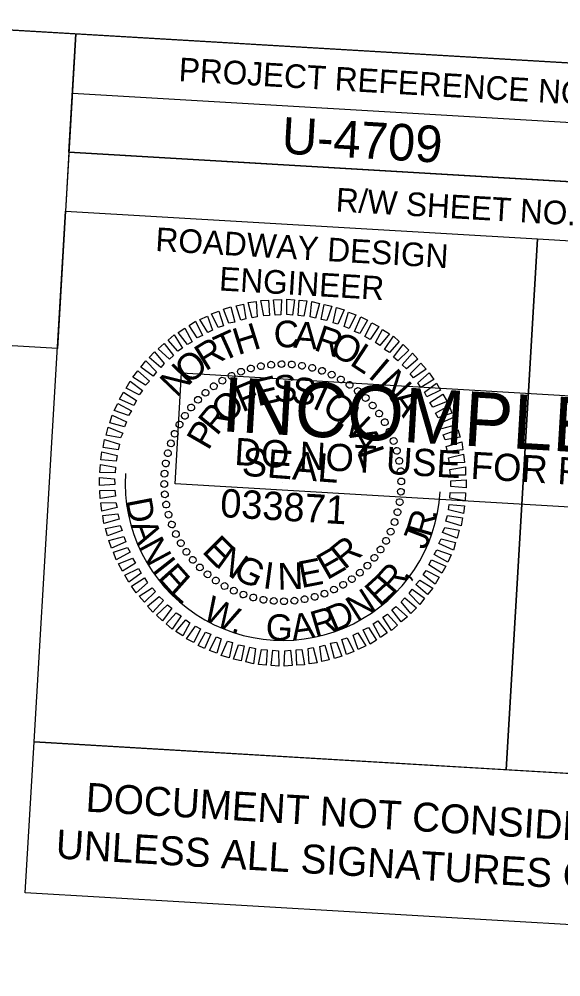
# Model space of a CAD drawing. Extents: x 2012145 to 2014096, y 444445 to 445643.
# Drawn here: x 2013858 to 2013972.6, y 445331.9 to 445534.5 of the extents above; entities that cross this region are included whole.
import ezdxf

# ---------------------------------------------------------------- set-up
doc = ezdxf.new("R2010")
doc.units = 0
for name, color, linetype in [('Old_Level_58', 7, 'Continuous'), ('Scratch_Level_0', 7, 'Continuous'), ('Sheet Data Field CELL', 7, 'Continuous'), ('Sheet Plan And Profile CELL', 7, 'Continuous'), ('Sheet Professional Seal CELL', 7, 'Continuous'), ('Sheet Profile Grid Minor CELL', 7, 'Continuous'), ('Sheet Sticker Exception Certification CELL', 7, 'Continuous'), ('Sheet Sticker Incomplete CELL', 7, 'Continuous')]:
    doc.layers.add(name, color=color, linetype=linetype)

msp = doc.modelspace()

# ---------------------------------------------------------------- linework, layer by layer
at = {"layer": 'Old_Level_58'}
msp.add_lwpolyline([(2013670.27, 445543.15), (2013869.97, 445531.38), (2013866.05, 445464.8), (2013666.34, 445476.57)], close=True, dxfattribs=at)
at = {"layer": 'Scratch_Level_0'}
msp.add_arc((2013913.73, 445436.43), 33.36, 176.6264, 356.6264, dxfattribs=at)
at = {"layer": 'Sheet Plan And Profile CELL'}
for p, q in [((2013869.23, 445518.85), (2014068.93, 445507.08)), ((2013868.5, 445506.37), (2013867.76, 445493.89)), ((2013868.5, 445506.37), (2014068.2, 445494.6)), ((2013967.64, 445488), (2013961.02, 445375.75))]:
    msp.add_line(p, q, dxfattribs=at)
for points in [[(2014069.67, 445519.6), (2012572.27, 445607.87), (2012510.48, 444559.69), (2014007.88, 444471.42)], [(2013869.97, 445531.38), (2014069.67, 445519.6), (2014068.2, 445494.6), (2013868.5, 445506.37)], [(2013867.76, 445493.89), (2013967.64, 445488), (2013961.02, 445375.7), (2013861.14, 445381.59)], [(2013967.64, 445488), (2014067.46, 445482.12), (2014060.84, 445369.81), (2013961.02, 445375.7)]]:
    msp.add_lwpolyline(points, close=True, dxfattribs=at)
at = {"layer": 'Sheet Professional Seal CELL'}
for p, q in [((2013904.9, 445459.94), (2013904.9, 445459.94)), ((2013906.94, 445460.62), (2013906.94, 445460.62)), ((2013909.07, 445461.1), (2013909.07, 445461.1)), ((2013911.29, 445461.37), (2013911.29, 445461.37)), ((2013913.46, 445461.54), (2013913.46, 445461.54)), ((2013915.66, 445461.46), (2013915.66, 445461.46)), ((2013917.84, 445461.18), (2013917.84, 445461.18)), ((2013919.97, 445460.7), (2013919.97, 445460.7)), ((2013922.04, 445460.13), (2013922.04, 445460.13)), ((2013900.93, 445458.02), (2013900.93, 445458.02)), ((2013902.89, 445459.06), (2013902.89, 445459.06)), ((2013924.09, 445459.31), (2013924.09, 445459.31)), ((2013926.04, 445458.29), (2013926.04, 445458.29)), ((2013899.11, 445456.88), (2013899.11, 445456.88)), ((2013927.93, 445457.18), (2013927.93, 445457.18)), ((2013895.78, 445454.02), (2013895.78, 445454.02)), ((2013897.37, 445455.47), (2013897.37, 445455.47)), ((2013929.65, 445455.83), (2013929.65, 445455.83)), ((2013931.32, 445454.38), (2013931.32, 445454.38)), ((2013894.33, 445452.35), (2013894.33, 445452.35)), ((2013932.78, 445452.79), (2013932.78, 445452.79)), ((2013892.98, 445450.62), (2013892.98, 445450.62)), ((2013934.18, 445451.05), (2013934.18, 445451.05)), ((2013891.87, 445448.74), (2013891.87, 445448.74)), ((2013935.32, 445449.23), (2013935.32, 445449.23)), ((2013890.85, 445446.79), (2013890.85, 445446.79)), ((2013936.36, 445447.27), (2013936.36, 445447.27)), ((2013890.03, 445444.74), (2013890.03, 445444.74)), ((2013937.24, 445445.26), (2013937.24, 445445.26)), ((2013889.45, 445442.67), (2013889.45, 445442.67)), ((2013937.92, 445443.22), (2013937.92, 445443.22)), ((2013888.98, 445440.54), (2013888.98, 445440.54)), ((2013938.4, 445441.09), (2013938.4, 445441.09)), ((2013888.7, 445438.36), (2013888.7, 445438.36)), ((2013938.67, 445438.87), (2013938.67, 445438.87)), ((2013888.62, 445436.16), (2013888.62, 445436.16)), ((2013913.73, 445436.43), (2013913.73, 445436.43)), ((2013938.84, 445436.7), (2013938.84, 445436.7)), ((2013888.79, 445433.99), (2013888.79, 445433.99)), ((2013938.76, 445434.5), (2013938.76, 445434.5)), ((2013889.06, 445431.77), (2013889.06, 445431.77)), ((2013938.48, 445432.32), (2013938.48, 445432.32)), ((2013889.54, 445429.64), (2013889.54, 445429.64)), ((2013938, 445430.19), (2013938, 445430.19)), ((2013890.22, 445427.6), (2013890.22, 445427.6)), ((2013937.43, 445428.12), (2013937.43, 445428.12)), ((2013891.1, 445425.59), (2013891.1, 445425.59)), ((2013936.61, 445426.06), (2013936.61, 445426.06)), ((2013892.14, 445423.63), (2013892.14, 445423.63)), ((2013935.59, 445424.12), (2013935.59, 445424.12)), ((2013893.28, 445421.81), (2013893.28, 445421.81)), ((2013934.48, 445422.23), (2013934.48, 445422.23)), ((2013894.68, 445420.07), (2013894.68, 445420.07)), ((2013933.13, 445420.51), (2013933.13, 445420.51)), ((2013896.14, 445418.48), (2013896.14, 445418.48)), ((2013930.09, 445417.38), (2013930.09, 445417.38)), ((2013931.68, 445418.84), (2013931.68, 445418.84)), ((2013897.81, 445417.03), (2013897.81, 445417.03)), ((2013899.53, 445415.68), (2013899.53, 445415.68)), ((2013928.35, 445415.98), (2013928.35, 445415.98)), ((2013901.42, 445414.57), (2013901.42, 445414.57)), ((2013903.37, 445413.55), (2013903.37, 445413.55)), ((2013924.57, 445413.8), (2013924.57, 445413.8)), ((2013926.53, 445414.84), (2013926.53, 445414.84)), ((2013905.42, 445412.73), (2013905.42, 445412.73)), ((2013907.49, 445412.15), (2013907.49, 445412.15)), ((2013909.62, 445411.68), (2013909.62, 445411.68)), ((2013911.8, 445411.4), (2013911.8, 445411.4)), ((2013914, 445411.32), (2013914, 445411.32)), ((2013916.17, 445411.49), (2013916.17, 445411.49)), ((2013918.39, 445411.76), (2013918.39, 445411.76)), ((2013920.52, 445412.24), (2013920.52, 445412.24)), ((2013922.56, 445412.92), (2013922.56, 445412.92))]:
    msp.add_line(p, q, dxfattribs=at)
for points in [[(2013904.84, 445470.81), (2013903.87, 445473.87), (2013905.44, 445474.23), (2013905.91, 445471.1)], [(2013907.27, 445471.32), (2013906.41, 445474.53), (2013908.13, 445474.78), (2013908.33, 445471.51)], [(2013909.7, 445471.73), (2013909.09, 445474.97), (2013910.75, 445475.02), (2013910.91, 445471.81)], [(2013912.11, 445471.89), (2013911.75, 445475.11), (2013913.46, 445475.21), (2013913.32, 445471.96)], [(2013914.62, 445471.99), (2013914.57, 445475.25), (2013916.21, 445475.1), (2013915.82, 445471.87)], [(2013917.02, 445471.8), (2013917.21, 445475.04), (2013918.85, 445474.89), (2013918.21, 445471.68)], [(2013919.5, 445471.5), (2013919.89, 445474.73), (2013921.52, 445474.34), (2013920.69, 445471.23)], [(2013921.88, 445470.96), (2013922.51, 445474.13), (2013924.15, 445473.78), (2013923.06, 445470.74)], [(2013900.09, 445469.24), (2013898.65, 445472.13), (2013900.24, 445472.74), (2013901.21, 445469.62)], [(2013902.34, 445470.16), (2013901.22, 445473.13), (2013902.75, 445473.64), (2013903.61, 445470.38)], [(2013924.39, 445470.26), (2013925.08, 445473.48), (2013926.75, 445472.98), (2013925.42, 445469.95)], [(2013926.75, 445469.47), (2013927.68, 445472.52), (2013929.2, 445471.93), (2013927.77, 445469.06)], [(2013895.6, 445467.05), (2013893.9, 445469.7), (2013895.26, 445470.58), (2013896.73, 445467.58)], [(2013897.87, 445468.17), (2013896.18, 445470.97), (2013897.78, 445471.68), (2013898.85, 445468.71)], [(2013928.94, 445468.44), (2013930.27, 445471.52), (2013931.64, 445470.84), (2013930.07, 445468.02)], [(2013931.13, 445467.36), (2013932.55, 445470.23), (2013934.06, 445469.44), (2013932.2, 445466.75)], [(2013893.61, 445465.66), (2013891.61, 445468.19), (2013893.02, 445469.15), (2013894.6, 445466.26)], [(2013933.36, 445466.08), (2013934.87, 445468.84), (2013936.32, 445467.9), (2013934.27, 445465.42)], [(2013891.53, 445464.23), (2013889.46, 445466.56), (2013890.73, 445467.69), (2013892.52, 445464.88)], [(2013935.23, 445464.61), (2013937.14, 445467.41), (2013938.38, 445466.28), (2013936.29, 445463.95)], [(2013887.92, 445460.79), (2013885.44, 445462.89), (2013886.61, 445464.12), (2013888.67, 445461.65)], [(2013889.78, 445462.58), (2013887.35, 445464.78), (2013888.67, 445465.86), (2013890.62, 445463.34)], [(2013937.18, 445463), (2013939.19, 445465.63), (2013940.43, 445464.46), (2013938.09, 445462.24)], [(2013886.31, 445458.98), (2013883.71, 445460.84), (2013884.75, 445462.23), (2013887.01, 445459.89)], [(2013938.99, 445461.34), (2013941.19, 445463.81), (2013942.32, 445462.54), (2013939.89, 445460.53)], [(2013884.69, 445457.07), (2013881.99, 445458.74), (2013883.07, 445460.07), (2013885.55, 445457.93)], [(2013940.68, 445459.48), (2013942.97, 445461.7), (2013944.09, 445460.43), (2013941.38, 445458.64)], [(2013883.37, 445455), (2013880.6, 445456.41), (2013881.44, 445457.92), (2013884.02, 445455.91)], [(2013942.32, 445457.58), (2013944.75, 445459.69), (2013945.72, 445458.28), (2013942.96, 445456.54)], [(2013943.71, 445455.55), (2013946.28, 445457.5), (2013947.14, 445456), (2013944.25, 445454.56)], [(2013882.24, 445452.76), (2013879.21, 445454.09), (2013880.05, 445455.59), (2013882.8, 445453.83)], [(2013944.88, 445453.43), (2013947.64, 445455.17), (2013948.5, 445453.61), (2013945.52, 445452.39)], [(2013881.11, 445450.62), (2013878.07, 445451.7), (2013878.81, 445453.21), (2013881.72, 445451.64)], [(2013946.05, 445451.15), (2013948.95, 445452.73), (2013949.51, 445451.15), (2013946.6, 445450.17)], [(2013880.22, 445448.27), (2013877.16, 445449.1), (2013877.61, 445450.73), (2013880.68, 445449.3)], [(2013946.92, 445448.95), (2013949.96, 445450.27), (2013950.51, 445448.64), (2013947.36, 445447.82)], [(2013879.43, 445445.91), (2013876.36, 445446.5), (2013876.81, 445448.17), (2013879.89, 445446.94)], [(2013947.68, 445446.55), (2013950.81, 445447.67), (2013951.26, 445446.09), (2013948.12, 445445.47)], [(2013878.88, 445443.39), (2013875.7, 445443.88), (2013876, 445445.57), (2013879.2, 445444.58)], [(2013948.34, 445444.11), (2013951.6, 445445.07), (2013951.81, 445443.4), (2013948.63, 445443.04)], [(2013878.49, 445441.01), (2013875.25, 445441.3), (2013875.45, 445442.94), (2013878.66, 445442.2)], [(2013948.8, 445441.67), (2013952, 445442.44), (2013952.2, 445440.72), (2013949.04, 445440.61)], [(2013878.29, 445438.52), (2013875.04, 445438.56), (2013875.14, 445440.26), (2013878.36, 445439.72)], [(2013949.11, 445439.25), (2013952.39, 445439.76), (2013952.44, 445438.05), (2013949.24, 445438.04)], [(2013878.19, 445436.02), (2013874.93, 445435.81), (2013874.93, 445437.51), (2013878.16, 445437.22)], [(2013949.27, 445436.84), (2013952.53, 445437.05), (2013952.53, 445435.34), (2013949.29, 445435.64)], [(2013878.35, 445433.61), (2013875.07, 445433.1), (2013875.02, 445434.8), (2013878.22, 445434.82)], [(2013949.17, 445434.34), (2013952.42, 445434.3), (2013952.32, 445432.6), (2013949.1, 445433.14)], [(2013878.66, 445431.18), (2013875.46, 445430.42), (2013875.26, 445432.14), (2013878.42, 445432.25)], [(2013948.97, 445431.85), (2013952.21, 445431.56), (2013952.01, 445429.92), (2013948.8, 445430.66)], [(2013879.12, 445428.75), (2013875.86, 445427.79), (2013875.65, 445429.46), (2013878.83, 445429.82)], [(2013948.58, 445429.47), (2013951.76, 445428.98), (2013951.46, 445427.29), (2013948.26, 445428.28)], [(2013879.78, 445426.31), (2013876.65, 445425.19), (2013876.2, 445426.77), (2013879.34, 445427.39)], [(2013948.03, 445426.94), (2013951.1, 445426.36), (2013950.65, 445424.69), (2013947.57, 445425.92)], [(2013880.54, 445423.91), (2013877.5, 445422.59), (2013876.95, 445424.22), (2013880.1, 445425.04)], [(2013947.24, 445424.59), (2013950.3, 445423.76), (2013949.85, 445422.13), (2013946.78, 445423.56)], [(2013881.41, 445421.71), (2013878.51, 445420.12), (2013877.95, 445421.71), (2013880.86, 445422.69)], [(2013946.35, 445422.24), (2013949.39, 445421.15), (2013948.65, 445419.65), (2013945.74, 445421.22)], [(2013882.58, 445419.43), (2013879.82, 445417.69), (2013878.96, 445419.25), (2013881.94, 445420.47)], [(2013945.22, 445420.1), (2013948.25, 445418.77), (2013947.41, 445417.26), (2013944.66, 445419.03)], [(2013883.75, 445417.31), (2013881.18, 445415.36), (2013880.32, 445416.86), (2013883.21, 445418.29)], [(2013944.09, 445417.86), (2013946.86, 445416.44), (2013946.02, 445414.94), (2013943.43, 445416.95)], [(2013885.14, 445415.28), (2013882.71, 445413.16), (2013881.74, 445414.57), (2013884.5, 445416.31)], [(2013942.76, 445415.78), (2013945.47, 445414.12), (2013944.39, 445412.78), (2013941.91, 445414.93)], [(2013886.78, 445413.38), (2013884.49, 445411.16), (2013883.36, 445412.42), (2013886.07, 445414.22)], [(2013941.15, 445413.88), (2013943.75, 445412.02), (2013942.71, 445410.63), (2013940.45, 445412.97)], [(2013888.47, 445411.52), (2013886.27, 445409.05), (2013885.14, 445410.32), (2013887.57, 445412.33)], [(2013939.54, 445412.07), (2013942.02, 445409.97), (2013940.85, 445408.74), (2013938.79, 445411.21)], [(2013890.28, 445409.86), (2013888.27, 445407.23), (2013887.03, 445408.4), (2013889.37, 445410.62)], [(2013937.68, 445410.27), (2013940.11, 445408.08), (2013938.79, 445407), (2013936.84, 445409.52)], [(2013892.23, 445408.25), (2013890.32, 445405.45), (2013889.08, 445406.58), (2013891.17, 445408.91)], [(2013894.1, 445406.78), (2013892.59, 445404.02), (2013891.14, 445404.95), (2013893.19, 445407.44)], [(2013935.93, 445408.62), (2013938, 445406.3), (2013936.73, 445405.17), (2013934.94, 445407.98)], [(2013896.33, 445405.5), (2013894.91, 445402.63), (2013893.4, 445403.42), (2013895.26, 445406.11)], [(2013931.86, 445405.81), (2013933.56, 445403.15), (2013932.2, 445402.28), (2013930.73, 445405.28)], [(2013933.84, 445407.19), (2013935.85, 445404.67), (2013934.44, 445403.7), (2013932.86, 445406.6)], [(2013898.52, 445404.42), (2013897.19, 445401.34), (2013895.82, 445402.02), (2013897.39, 445404.84)], [(2013900.71, 445403.39), (2013899.78, 445400.34), (2013898.26, 445400.93), (2013899.69, 445403.8)], [(2013927.37, 445403.62), (2013928.8, 445400.73), (2013927.22, 445400.12), (2013926.25, 445403.24)], [(2013929.59, 445404.69), (2013931.28, 445401.89), (2013929.68, 445401.18), (2013928.61, 445404.15)], [(2013903.07, 445402.6), (2013902.38, 445399.38), (2013900.71, 445399.88), (2013902.04, 445402.91)], [(2013905.58, 445401.9), (2013904.95, 445398.73), (2013903.31, 445399.08), (2013904.39, 445402.12)], [(2013907.96, 445401.36), (2013907.56, 445398.13), (2013905.94, 445398.52), (2013906.77, 445401.63)], [(2013910.44, 445401.06), (2013910.25, 445397.82), (2013908.61, 445397.96), (2013909.25, 445401.18)], [(2013920.19, 445401.54), (2013921.05, 445398.33), (2013919.33, 445398.08), (2013919.12, 445401.35)], [(2013922.62, 445402.05), (2013923.59, 445398.98), (2013922.02, 445398.63), (2013921.55, 445401.76)], [(2013925.11, 445402.7), (2013926.24, 445399.73), (2013924.71, 445399.22), (2013923.85, 445402.47)], [(2013912.84, 445400.87), (2013912.89, 445397.61), (2013911.25, 445397.76), (2013911.64, 445400.99)], [(2013915.35, 445400.97), (2013915.71, 445397.75), (2013914, 445397.65), (2013914.14, 445400.89)], [(2013917.76, 445401.13), (2013918.37, 445397.89), (2013916.71, 445397.84), (2013916.55, 445401.05)]]:
    msp.add_lwpolyline(points, close=True, dxfattribs=at)
for centre, major_axis in [((2013911.27, 445461.39), (-0.071, 0.717)), ((2013913.46, 445461.51), (-0.008, 0.72)), ((2013915.64, 445461.44), (0.055, 0.718)), ((2013917.81, 445461.17), (0.117, 0.71)), ((2013904.89, 445459.9), (-0.254, 0.674)), ((2013906.97, 445460.58), (-0.194, 0.693)), ((2013909.1, 445461.08), (-0.133, 0.708)), ((2013919.96, 445460.72), (0.179, 0.697)), ((2013922.05, 445460.09), (0.239, 0.679)), ((2013924.08, 445459.27), (0.297, 0.656)), ((2013900.95, 445458.01), (-0.367, 0.62)), ((2013902.88, 445459.04), (-0.311, 0.649)), ((2013926.03, 445458.28), (0.353, 0.627)), ((2013927.89, 445457.13), (0.407, 0.594)), ((2013897.4, 445455.46), (-0.469, 0.546)), ((2013899.12, 445456.82), (-0.419, 0.585)), ((2013929.64, 445455.82), (0.457, 0.557)), ((2013895.8, 445453.97), (-0.515, 0.504)), ((2013931.27, 445454.36), (0.504, 0.515)), ((2013894.34, 445452.34), (-0.557, 0.457)), ((2013932.76, 445452.76), (0.546, 0.469)), ((2013934.12, 445451.04), (0.585, 0.419)), ((2013893.03, 445450.59), (-0.594, 0.407)), ((2013935.31, 445449.21), (0.62, 0.367)), ((2013891.87, 445448.73), (-0.627, 0.353)), ((2013936.34, 445447.28), (0.649, 0.311)), ((2013890.88, 445446.78), (-0.656, 0.297)), ((2013937.2, 445445.26), (0.674, 0.254)), ((2013890.07, 445444.75), (-0.679, 0.239)), ((2013937.88, 445443.18), (0.693, 0.194)), ((2013889.43, 445442.66), (-0.697, 0.179)), ((2013938.38, 445441.05), (0.708, 0.133)), ((2013888.98, 445440.51), (-0.71, 0.117)), ((2013938.69, 445438.89), (0.717, 0.071)), ((2013888.72, 445438.34), (-0.718, 0.055)), ((2013888.65, 445436.16), (-0.72, -0.008)), ((2013938.81, 445436.7), (0.72, 0.008)), ((2013888.77, 445433.97), (-0.717, -0.071)), ((2013938.74, 445434.52), (0.718, -0.055)), ((2013889.08, 445431.8), (-0.708, -0.133)), ((2013938.47, 445432.34), (0.71, -0.117)), ((2013889.58, 445429.67), (-0.693, -0.194)), ((2013938.02, 445430.2), (0.697, -0.179)), ((2013890.26, 445427.59), (-0.674, -0.254)), ((2013937.39, 445428.11), (0.679, -0.239)), ((2013891.12, 445425.58), (-0.649, -0.311)), ((2013936.57, 445426.08), (0.656, -0.297)), ((2013892.15, 445423.65), (-0.62, -0.367)), ((2013935.59, 445424.13), (0.627, -0.353)), ((2013893.34, 445421.82), (-0.585, -0.419)), ((2013934.43, 445422.27), (0.594, -0.407)), ((2013894.69, 445420.1), (-0.546, -0.469)), ((2013931.66, 445418.89), (0.515, -0.504)), ((2013933.12, 445420.52), (0.557, -0.457)), ((2013896.19, 445418.5), (-0.504, -0.515)), ((2013897.82, 445417.04), (-0.457, -0.557)), ((2013930.06, 445417.39), (0.469, -0.546)), ((2013899.57, 445415.73), (-0.407, -0.594)), ((2013901.43, 445414.57), (-0.353, -0.627)), ((2013926.51, 445414.85), (0.367, -0.62)), ((2013928.34, 445416.04), (0.419, -0.585)), ((2013903.38, 445413.58), (-0.297, -0.656)), ((2013905.41, 445412.77), (-0.239, -0.679)), ((2013922.56, 445412.96), (0.254, -0.674)), ((2013924.58, 445413.82), (0.311, -0.649)), ((2013907.5, 445412.13), (-0.179, -0.697)), ((2013909.64, 445411.68), (-0.117, -0.71)), ((2013911.82, 445411.42), (-0.055, -0.718)), ((2013914, 445411.35), (0.008, -0.72)), ((2013916.19, 445411.47), (0.071, -0.717)), ((2013918.35, 445411.78), (0.133, -0.708)), ((2013920.49, 445412.28), (0.194, -0.693))]:
    msp.add_ellipse(centre, major_axis=major_axis, ratio=0.999708, dxfattribs=at)
at = {"layer": 'Sheet Sticker Exception Certification CELL'}
for p, q in [((2013859.26, 445349.68), (2013861.14, 445381.6)), ((2013861.14, 445381.6), (2014060.84, 445369.83)), ((2014058.96, 445337.91), (2013859.26, 445349.68))]:
    msp.add_line(p, q, dxfattribs=at)
at = {"layer": 'Sheet Sticker Incomplete CELL'}
msp.add_lwpolyline([(2013890.95, 445436.18), (2013892.34, 445459.64), (2014039.08, 445450.99), (2014037.7, 445427.53)], close=True, dxfattribs=at)

# ---------------------------------------------------------------- texts
at = {"layer": 'Sheet Data Field CELL'}
msp.add_text('U-4709', height=7.75, rotation=356.6264, dxfattribs=at).set_placement((2013913.36, 445506.08))
at = {"layer": 'Sheet Plan And Profile CELL'}
for s, height, p in [('PROJECT REFERENCE NO.', 5.0001, (2013891.62, 445521.39)), ('R/W SHEET NO.', 5.0001, (2013924.86, 445493.83)), ('ROADWAY DESIGN', 5.0001, (2013886.7, 445485.46)), ('ENGINEER', 5, (2013900.18, 445477.11))]:
    msp.add_text(s, height=height, rotation=356.6264, dxfattribs=at).set_placement(p)
at = {"layer": 'Sheet Professional Seal CELL'}
for s, height, rotation, p in [('H', 5.64, 17.2459, (2013904.25, 445463.38)), ('C', 5.64, 2.8463, (2013911.95, 445464.93)), ('A', 5.64, 355.6467, (2013915.91, 445465)), ('T', 5.64, 24.4462, (2013900.91, 445461.93)), ('R', 5.64, 341.2475, (2013920.1, 445464.55)), ('O', 5.64, 334.0476, (2013923.4, 445463.61)), ('R', 5.64, 31.6469, (2013897.38, 445459.93)), ('O', 5.64, 38.8482, (2013893.76, 445457.04)), ('L', 5.64, 326.8473, (2013927.68, 445461.5)), ('I', 5.64, 319.6466, (2013931.58, 445458.87)), ('N', 5.64, 46.0499, (2013891.29, 445454.28)), ('N', 5.64, 312.4453, (2013933.64, 445457.19)), ('F', 5.64, 22.5935, (2013905.14, 445451.26)), ('E', 5.64, 13.2375, (2013908.42, 445452.57)), ('S', 5.64, 3.882, (2013911.93, 445453.41)), ('S', 5.64, 354.5268, (2013915.52, 445453.25)), ('I', 5.64, 335.816, (2013919.77, 445452.3)), ('O', 5.64, 41.3077, (2013901.67, 445448.51)), ('O', 5.64, 326.4599, (2013921.73, 445451.48)), ('A', 5.64, 305.2436, (2013936.41, 445454.08)), ('R', 5.64, 50.6661, (2013899.78, 445446.17)), ('N', 5.64, 317.103, (2013924.96, 445449.29)), ('P', 5.64, 60.0253, (2013897.99, 445443.07)), ('A', 5.64, 298.3867, (2013927.65, 445446.53)), ('SEAL', 5.998, 355.6264, (2013904.95, 445437.95)), ('L', 5.64, 289.0273, (2013929.39, 445442.97)), ('E', 5.64, 314.9033, (2013896.44, 445421.77)), ('R', 5.64, 39.1078, (2013926.76, 445417.88)), ('N', 5.64, 324.2604, (2013899.27, 445418.9)), ('E', 5.64, 29.7505, (2013923.08, 445415.74)), ('G', 5.64, 333.6167, (2013902.93, 445416.43)), ('I', 5.64, 352.3276, (2013909.36, 445414.15)), ('N', 5.64, 1.6828, (2013912.7, 445413.8)), ('E', 5.64, 11.0382, (2013917.67, 445414.11))]:
    msp.add_text(s, height=height, rotation=rotation, dxfattribs=at).set_placement(p)
at = {"layer": 'Sheet Profile Grid Minor CELL'}
for s, height, rotation, p in [('033871', 5.998, 356.6264, (2013900.38, 445429.19)), ('D', 5.5, 280.8946, (2013880.46, 445432.74)), ('R', 5.5, 73.9805, (2013945.06, 445424.66)), ('.', 5.5, 80.9069, (2013946.25, 445428.53)), ('A', 5.5, 290.0393, (2013881.47, 445427.5)), ('J', 5.5, 69.1119, (2013943.95, 445422.05)), ('N', 5.5, 298.2251, (2013883.07, 445423)), ('I', 5.5, 308.1568, (2013885.85, 445417.91)), ('E', 5.5, 311.6772, (2013887.04, 445416.23)), ('R', 5.5, 49.0052, (2013937.16, 445412.53)), ('L', 5.5, 318.2602, (2013889.53, 445413.31)), ('E', 5.5, 42.4222, (2013934.27, 445410)), (',', 5.5, 55.9317, (2013939.88, 445415.53)), ('N', 5.5, 32.4905, (2013929.41, 445406.86)), ('W', 5.5, 333.5156, (2013896.47, 445407.75)), ('R', 5.5, 16.4194, (2013920.61, 445403.67)), ('D', 5.5, 23.3459, (2013924.51, 445404.74)), ('G', 5.5, 358.3019, (2013910.08, 445403.16)), ('A', 5.5, 8.2337, (2013915.87, 445403.03)), ('.', 5.5, 345.1217, (2013902.59, 445404.87))]:
    msp.add_text(s, height=height, rotation=rotation, dxfattribs=at).set_placement(p)
at = {"layer": 'Sheet Sticker Exception Certification CELL'}
for s, p in [('DOCUMENT NOT CONSIDERED FINAL', (2013871.92, 445366.87)), ('UNLESS ALL SIGNATURES COMPLETED', (2013865.59, 445356.96))]:
    msp.add_text(s, height=6.124, rotation=356.6264, dxfattribs=at).set_placement(p)
at = {"layer": 'Sheet Sticker Incomplete CELL'}
for s, height, p in [('INCOMPLETE PLANS', 11.52, (2013900.58, 445447.33)), ('DO NOT USE FOR R/W ACQUISITION', 5.76, (2013903.41, 445440.2))]:
    msp.add_text(s, height=height, rotation=356.6264, dxfattribs=at).set_placement(p)

doc.saveas('drawing.dxf')
